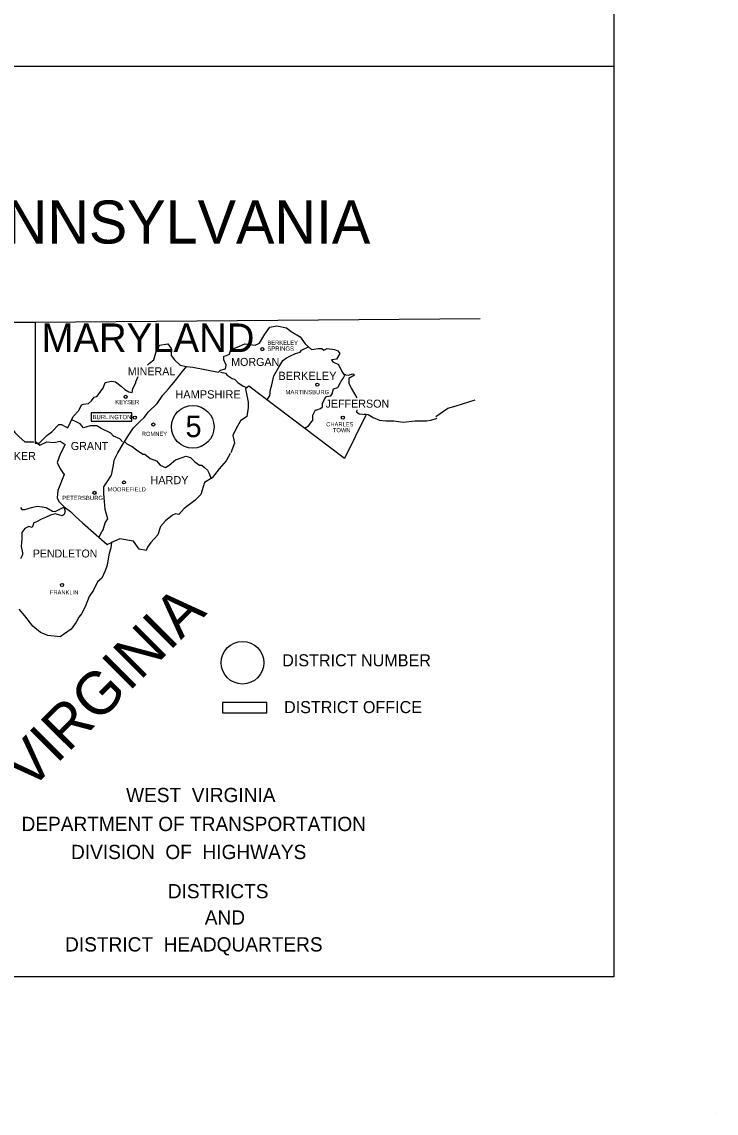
# Model space of a CAD drawing. Extents: x -2.1 to 5.9, y -23.5 to -12.8.
# Drawn here: x 4.174 to 5.87, y -23.468 to -20.801 of the extents above; entities that cross this region are included whole.
import ezdxf

# ---------------------------------------------------------------- set-up
doc = ezdxf.new("R2010")
doc.units = 0
doc.layers.add('Construction Line', color=7, linetype='Continuous')

msp = doc.modelspace()

# ---------------------------------------------------------------- linework, layer by layer
at = {"layer": 'Construction Line'}
for p, q in [((5.62, -13.1346), (5.62, -23.1348)), ((5.62, -20.9101), (-1.8802, -20.9101)), ((5.62, -23.1348), (-1.8802, -23.1348)), ((5.87, -23.4678), (5.87, -23.4678))]:
    msp.add_line(p, q, dxfattribs=at)
for points in [[(3.7346, -20.991), (3.7363, -21.5355), (4.206, -21.5355), (4.206, -21.8304)], [(4.206, -21.5355), (5.2936, -21.5262)], [(4.4811, -21.6403), (4.4859, -21.6352), (4.4961, -21.627), (4.5012, -21.61), (4.51, -21.5916), (4.5301, -21.5882), (4.5386, -21.5998), (4.5386, -21.6168), (4.5471, -21.627), (4.5604, -21.6403), (4.576, -21.6437), (4.5913, -21.6454), (4.6539, -21.6576), (4.659, -21.6525), (4.6709, -21.6488), (4.6726, -21.6403), (4.6675, -21.627), (4.6675, -21.6185), (4.674, -21.6168), (4.6808, -21.6134), (4.6842, -21.6015), (4.6998, -21.5964), (4.7182, -21.5882), (4.744, -21.5916), (4.7542, -21.5862), (4.7675, -21.5641), (4.7794, -21.5474), (4.7967, -21.544), (4.8202, -21.5491), (4.8321, -21.5576), (4.8539, -21.5709), (4.8661, -21.5882), (4.8811, -21.6015), (4.8981, -21.5998), (4.9066, -21.5998), (4.9114, -21.6032), (4.9199, -21.5998), (4.9372, -21.6015), (4.9457, -21.6049), (4.9508, -21.6117), (4.9423, -21.6253), (4.9304, -21.627), (4.9338, -21.6321), (4.9474, -21.6386), (4.9556, -21.6559), (4.9607, -21.6627), (4.9709, -21.6644), (4.9831, -21.661), (4.9865, -21.6644), (4.9726, -21.6726), (4.9726, -21.6845), (4.978, -21.6964), (4.9865, -21.7103), (4.9922, -21.7197)], [(4.7743, -21.7236), (4.7794, -21.7151), (4.7811, -21.6998), (4.7845, -21.6879), (4.7896, -21.6661), (4.8012, -21.6454), (4.8117, -21.6287), (4.8202, -21.6219), (4.8287, -21.6185), (4.842, -21.6117), (4.8539, -21.6083), (4.8573, -21.6032), (4.8743, -21.595)], [(4.3627, -22.0608), (4.3655, -22.0545), (4.3689, -22.0474), (4.3723, -22.0423), (4.3774, -22.0256), (4.3842, -22.0154), (4.3774, -21.993), (4.3757, -21.9729), (4.374, -21.9545), (4.374, -21.9375), (4.3825, -21.9253), (4.3927, -21.9086), (4.3981, -21.8848), (4.3992, -21.8726), (4.408, -21.8542), (4.4216, -21.8324), (4.4352, -21.81), (4.4468, -21.7933), (4.4624, -21.778), (4.4726, -21.7678), (4.4828, -21.7539), (4.5046, -21.7338), (4.5179, -21.7137), (4.5318, -21.6981), (4.5403, -21.6879), (4.5488, -21.6777), (4.559, -21.6644), (4.576, -21.6437)], [(4.206, -21.8304), (4.2162, -21.8304), (4.2352, -21.8117), (4.2468, -21.8032), (4.2638, -21.7848), (4.2706, -21.7848), (4.2794, -21.7899), (4.2859, -21.7933), (4.2995, -21.7658), (4.3131, -21.7508), (4.3196, -21.7372), (4.3247, -21.7355), (4.3366, -21.7338), (4.3437, -21.727), (4.3505, -21.7185), (4.3573, -21.7171), (4.3723, -21.6964), (4.3774, -21.6828), (4.3927, -21.6794), (4.4029, -21.6811), (4.4165, -21.6913), (4.425, -21.6998), (4.4352, -21.7052), (4.4434, -21.7069), (4.4451, -21.6981), (4.4519, -21.6828), (4.4519, -21.6811), (4.4573, -21.6695), (4.4581, -21.6681)], [(4.659, -21.6576), (4.6709, -21.6593), (4.6757, -21.6644), (4.6876, -21.6726), (4.693, -21.6746), (4.7015, -21.6828), (4.7148, -21.6913), (4.7233, -21.6947)], [(4.8661, -21.7933), (4.8743, -21.7882), (4.8794, -21.7814), (4.8845, -21.7746), (4.8845, -21.7624), (4.8879, -21.7556), (4.8913, -21.7491), (4.8947, -21.7491), (4.9032, -21.7457), (4.9083, -21.7423), (4.9083, -21.7338), (4.9131, -21.7236), (4.9182, -21.7171), (4.9287, -21.7151), (4.9321, -21.7103), (4.9355, -21.6981), (4.9457, -21.6947), (4.9522, -21.6828), (4.9539, -21.6794), (4.959, -21.6726), (4.9641, -21.661)], [(4.9922, -21.7497), (4.9916, -21.7539), (4.9981, -21.759), (5.0151, -21.7607), (4.9624, -21.8678), (4.7284, -21.6913), (4.7202, -21.6981), (4.7267, -21.7304), (4.7267, -21.744), (4.7233, -21.7658), (4.708, -21.7763), (4.6964, -21.7964), (4.6896, -21.8117), (4.6913, -21.8222), (4.693, -21.8304), (4.6842, -21.8542)], [(5.1848, -21.7658), (5.2143, -21.7454), (5.2347, -21.7398), (5.2814, -21.725)], [(5.01, -21.759), (5.0202, -21.7607), (5.0318, -21.7678), (5.0474, -21.7746), (5.0627, -21.7763), (5.0828, -21.7763), (5.1052, -21.7797), (5.1338, -21.7763), (5.1505, -21.7763), (5.1627, -21.7763), (5.1729, -21.7746), (5.1882, -21.7695)], [(4.0315, -21.8967), (4.0332, -21.8848), (4.0417, -21.8678), (4.0482, -21.844), (4.0536, -21.8205), (4.057, -21.8134), (4.0587, -21.7964), (4.0788, -21.7913), (4.089, -21.7882), (4.1026, -21.7814), (4.1267, -21.7882), (4.1366, -21.7913), (4.1485, -21.7933), (4.1567, -21.8049), (4.1669, -21.8151), (4.1808, -21.8273), (4.2029, -21.8273)], [(4.4199, -21.8273), (4.4131, -21.8205), (4.3981, -21.8134), (4.391, -21.8066), (4.3672, -21.795), (4.3573, -21.7882), (4.3403, -21.7882), (4.3247, -21.7933), (4.3162, -21.7831), (4.3046, -21.778), (4.2978, -21.7746)], [(4.2077, -21.8273), (4.2179, -21.8358), (4.2352, -21.8273), (4.2519, -21.829), (4.2672, -21.8256), (4.2794, -21.8338), (4.2672, -21.8576), (4.2604, -21.8777), (4.2672, -21.8933), (4.2771, -21.9069), (4.2621, -21.946), (4.2604, -21.9644), (4.2638, -21.9729), (4.2771, -21.9865), (4.2927, -21.9981), (4.3046, -22.0103), (4.3216, -22.0256), (4.3825, -22.078), (4.3927, -22.0732)], [(4.425, -21.8273), (4.4301, -21.8324), (4.4434, -21.8389), (4.4536, -21.8474), (4.4692, -21.8576), (4.4743, -21.8576), (4.4876, -21.8678), (4.5029, -21.8743), (4.5117, -21.8848), (4.525, -21.8899), (4.5335, -21.8848), (4.5488, -21.8712), (4.5655, -21.8661), (4.5743, -21.8627), (4.5862, -21.8661), (4.5961, -21.876), (4.608, -21.8848), (4.6131, -21.8848), (4.6199, -21.8899), (4.627, -21.8967), (4.6304, -21.9035), (4.6355, -21.9151)], [(4.6825, -21.8559), (4.6726, -21.8743), (4.6556, -21.8933), (4.6386, -21.9151), (4.6199, -21.927), (4.6114, -21.9559), (4.5961, -21.9712), (4.5706, -21.9902), (4.557, -22.0052), (4.5488, -22.0035), (4.542, -22.0069), (4.525, -22.0205), (4.5128, -22.0341), (4.5063, -22.0545), (4.4893, -22.0732), (4.4808, -22.0848), (4.4774, -22.0933), (4.4607, -22.0899), (4.4468, -22.0698), (4.4131, -22.0647), (4.3927, -22.0732), (4.391, -22.0865), (4.3859, -22.1035), (4.3825, -22.129), (4.3774, -22.1426), (4.3689, -22.161), (4.3587, -22.1698), (4.3488, -22.1902), (4.3383, -22.2052), (4.3281, -22.231), (4.3196, -22.2477), (4.3131, -22.2562), (4.3063, -22.2681), (4.2944, -22.2848), (4.2672, -22.3038), (4.2369, -22.3004), (4.2196, -22.2936), (4.2009, -22.278), (4.1808, -22.2528), (4.1669, -22.2361)], [(4.1706, -21.9882), (4.174, -21.993), (4.1808, -21.993), (4.1975, -21.9882), (4.2111, -21.9848), (4.2233, -21.9865), (4.2332, -21.9882), (4.2485, -21.997), (4.2553, -21.9981), (4.276, -21.9871), (4.2794, -21.997), (4.2771, -22.0052), (4.2723, -22.0086), (4.2553, -22.0035), (4.2434, -22.0069), (4.2318, -22.012), (4.2233, -22.0154), (4.2077, -22.0239), (4.2029, -22.0256), (4.1992, -22.0372), (4.191, -22.0341), (4.1808, -22.0389), (4.174, -22.0491), (4.174, -22.0647), (4.1723, -22.0831), (4.1757, -22.0984), (4.1757, -22.1035), (4.1706, -22.1134)]]:
    msp.add_lwpolyline(points, dxfattribs=at)
for points in [[(4.4426, -21.7565), (4.3428, -21.7565), (4.3428, -21.7769), (4.4426, -21.7769)], [(4.6642, -22.4641), (4.6642, -22.4893), (4.7719, -22.4893), (4.7719, -22.4641)]]:
    msp.add_lwpolyline(points, close=True, dxfattribs=at)
for centre, radius in [((4.7612, -21.601), 0.00381), ((4.8956, -21.6878), 0.00381), ((4.4275, -21.7174), 0.00381), ((4.5912, -21.7909), 0.0521), ((4.4497, -21.7682), 0.00381), ((4.4951, -21.7851), 0.00381), ((4.9578, -21.7684), 0.00381), ((4.4232, -21.9267), 0.00381), ((4.3514, -21.952), 0.00381), ((4.2721, -22.1771), 0.00381), ((4.7129, -22.3671), 0.0521)]:
    msp.add_circle(centre, radius, dxfattribs=at)

# ---------------------------------------------------------------- texts
for s, height, p in [('PENNSYLVANIA', 0.105101, (3.9471, -21.3429)), ('MARYLAND', 0.06998, (4.2219, -21.6083)), ('SPRINGS', 0.01048, (4.7735, -21.6049)), ('BERKELEY', 0.0102, (4.7738, -21.5905)), ('MORGAN', 0.01955, (4.6851, -21.642)), ('MINERAL', 0.01955, (4.4325, -21.665)), ('BERKELEY', 0.02011, (4.8005, -21.6763)), ('HAMPSHIRE', 0.02011, (4.5487, -21.7216)), ('MARTINSBURG', 0.010481, (4.8178, -21.7112)), ('KEYSER', 0.01048, (4.4018, -21.7355)), ('JEFFERSON', 0.01955, (4.9158, -21.744)), ('BURLINGTON', 0.01048, (4.3466, -21.7721)), ('5', 0.0527, (4.5736, -21.816)), ('CHARLES', 0.0102, (4.9173, -21.7896)), ('ROMNEY', 0.0102, (4.4668, -21.8131)), ('TOWN', 0.0102, (4.9336, -21.8041)), ('GRANT', 0.01955, (4.2934, -21.8474)), ('TUCKER', 0.01955, (4.1005, -21.8718)), ('HARDY', 0.01983, (4.4879, -21.931)), ('MOOREFIELD', 0.0102, (4.3835, -21.9486)), ('PETERSBURG', 0.01048, (4.2724, -21.9698)), ('PENDLETON', 0.01926, (4.2008, -22.11)), ('FRANKLIN', 0.0102, (4.2423, -22.2004)), ('DISTRICT NUMBER', 0.029462, (4.8098, -22.376)), ('DISTRICT OFFICE', 0.029462, (4.8143, -22.4904)), ('WEST  VIRGINIA', 0.034844, (4.4284, -22.7079)), ('DEPARTMENT OF TRANSPORTATION', 0.034844, (4.1731, -22.7785)), ('DIVISION  OF  HIGHWAYS', 0.034844, (4.294, -22.847)), ('DISTRICTS', 0.03484, (4.5304, -22.9428)), ('AND', 0.03484, (4.6207, -23.0071)), ('DISTRICT  HEADQUARTERS', 0.034844, (4.2795, -23.0728))]:
    msp.add_text(s, height=height, dxfattribs=at).set_placement(p)
msp.add_text('VIRGINIA', height=0.10497, rotation=45, dxfattribs=at).set_placement((4.1927, -22.6823))

doc.saveas('drawing.dxf')
